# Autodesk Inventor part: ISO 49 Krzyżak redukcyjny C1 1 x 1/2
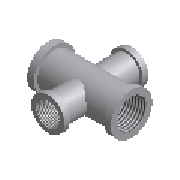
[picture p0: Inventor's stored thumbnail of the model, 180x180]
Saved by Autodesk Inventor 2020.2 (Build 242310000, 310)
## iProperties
Manager: www.cadconsulting.pl
Company: Fabian Stasiak CAD Consulting
Created: 2014-02
Part Number: ISO 49 Krzyżak redukcyjny C1 1 x 1/2
Material: Żelazo, ciągliwe
Description: Elementy z żeliwa ciągliwego - Czwórniki redukcyjne C1
Document SubType Name: Modeling
Standard: ISO 49
Designer: F.Stasiak
Standard Revision: Second edition 1994-12-15
Standards Organization: ISO
Language: pl-PL
Size Designation: 1 x 1/2
Categories: <MemberInstance><Categories><Category DisplayName="Rury cienko- i grubościenne" InternalName="4347fa0f-2144-441d-94cd-e3e15c92b736" Mnemonic="TUBEANDPIPE"><Cate
Density: 7.15 g/cm^3
Appearance: Częściowo polerowana
Catalog Web Link: www.expertbooks.pl
NAME: PIPING: ISO 49 Reducing Cross C1
DATA: <meta><inlinegroups number="2" deflen="5.2"></inlinegroups><connections number="4"></connections><angles><a>3.14159265358979</a><a>1.57079632679489</a><a>1.5707
IsCustomPart: 0
Author: F.Stasiak
Subject: Zbiór ćwiczeń. Autodesk Inventor 2020. Kurs Professional
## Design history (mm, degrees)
sketch "Sketch1"
  geometry: L1 (0, 0)-(64, 0); L2 (64, 0)-(64, 15.146); L3 (32, 0)-(32, 17); L4 (0, 0)-(0, 15.146); L5 (0, 15.146)-(17, 14.614); L6 (64, 15.146)-(47, 14.614); L7 (0, 15.146)-(0, 20.4); L8 (64, 15.146)-(64, 20.4); L9 (17, 14.614)-(47, 14.614); L10 (6.8, 17)-(57.2, 17); L11 (0, 20.4)-(6.8, 20.4); L12 (6.8, 20.4)-(6.8, 17); L13 (64, 20.4)-(57.2, 20.4); L14 (57.2, 20.4)-(57.2, 17); L15 (0, 15.146)-(0, 0); L16 (64, 0)-(0, 0); L17 (64, 0)-(64, 15.146); L18 (47, 14.614)-(47, 0); L19 (17, 14.614)-(17, 0)
  constraints: 38 end point, 7 perpendicular, 5 symmetric about line, 3 parallel, 2 midpoint, 2 point on line, 1 collinear, 1 horizontal, 5 other
  dimensions: "d0" = 30.291 diameter of L4.end L1 (= MD1); "d1" = 17 horizontal distance of L4.end L5.end (= a - z1); "d2" = 32 distance between parallel lines of L3 L4 (= a); "d3" = 1.78991 deg angle of L1 L5; "d4" = 6.8 distance of L7.end L11.end (= EE1); "d5" = 40.8 diameter of L11 L1 (= H1); "d6" = 34 diameter of L10 L1 (= D1)
revolve "Revolution1" stored, may be unused: angle "d8" = 90 deg
sketch "Sketch2"
  geometry: L1 (-64, 0)-(0, 0); L2 (-32, 34)-(-32, -34); L3 (-22.684, -34)-(-18.98, -34); L4 (-18.98, -34)-(-18.98, -29.66); L5 (-18.98, -29.66)-(-21.15, -29.66); L6 (-21.15, -29.66)-(-21.15, 29.66); L7 (-22.684, -34)-(-23.091, -21); L8 (-23.091, -21)-(-23.091, 21); L9 (-32, 0)-(-21.15, 0); L10 (-32, -34)-(-22.684, -34); L11 (-22.685, 34)-(-23.091, 21); L12 (-32, 34)-(-22.685, 34); L13 (-22.685, 34)-(-18.98, 34); L14 (-18.98, 34)-(-18.98, 29.66); L15 (-18.98, 29.66)-(-21.15, 29.66); L16 (-22.685, 34)-(-32, 34); L17 (-32, -34)-(-22.684, -34); L18 (-32, -34)-(-32, 34); L19 (0, 20.4)-(0, -20.4) reference; L20 (-64, 20.4)-(-64, -20.4) reference; L21 (-23.091, 21)-(-32, 21); L22 (-23.091, -21)-(-32, -21)
  constraints: 40 end point, 7 parallel, 5 midpoint, 5 perpendicular, 5 symmetric about line, 2 point on line, 1 collinear, 5 other
  dimensions: "d7" = 18.631 diameter of L3.start L2 (= MD2); "d9" = 26.04 diameter of L4 L2 (= H2); "d10" = 21.7 diameter of L6 L2 (= D2); "d11" = 1.78991 deg angle of L2 L7; "d12" = 34 distance between parallel lines of L10 L9 (= b); "d13" = 13 vertical distance of L3.start L7.end (= b - z2); "d14" = 4.34 distance of L3.end L4.end (= EE2)
revolve "Revolution2" stored, may be unused: angle "d55" = 90 deg
revolve "Revolution3" stored, may be unused: angle "d56" = 90 deg
revolve "Revolution4" stored, may be unused: angle "d57" = 90 deg
workpoint "Work Point1"
workpoint "Work Point2"
workpoint "Work Point3"
workpoint "Work Point4"
workaxis "Work Axis1"
workpoint "Work Point5"
workaxis "Work Axis2"
workpoint "Work Point6"
workaxis "Work Axis3"
workpoint "Work Point7"
workaxis "Work Axis4"
workpoint "Work Point8"
body "Solid1"
feature "Gwint1" dims "d23" = 10, "d24" = 0
feature "Gwint2" dims "d25" = 10, "d26" = 0
feature "Gwint3" dims "d58" = 10, "d59" = 0
feature "Gwint4" dims "d60" = 10, "d61" = 0
other parameters: "a" = 32 [user parameter; used in 2 equation terms], "D1" = 34 [user parameter; used in 1 equation term], "MD1" = 30.291 [user parameter; used in 1 equation term], "z1" = 15 [user parameter; used in 1 equation term], "H1" = 40.8 [user parameter; used in 1 equation term], "EE1" = 6.8 [user parameter; used in 1 equation term], "b" = 34 [user parameter; used in 2 equation terms], "D2" = 21.7 [user parameter; used in 1 equation term], "MD2" = 18.631 [user parameter; used in 1 equation term], "z2" = 21 [user parameter; used in 1 equation term], "H2" = 26.04 [user parameter; used in 1 equation term], "EE2" = 4.34 [user parameter; used in 1 equation term], "Size_Designation" = 12.345 [user parameter]
